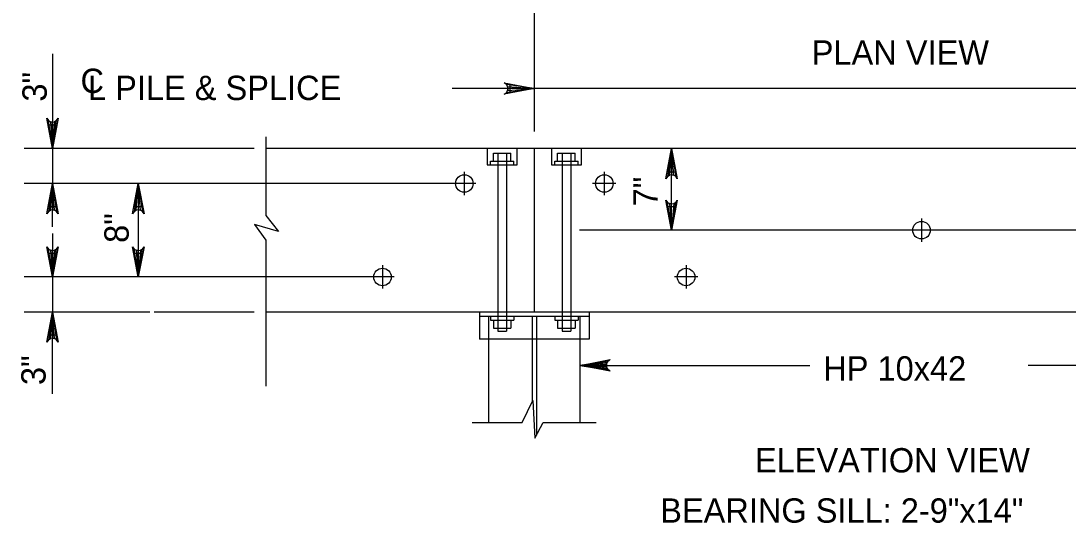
# Model space of a CAD drawing. Extents: x 638304 to 640306, y 296653 to 298435.
# Drawn here: x 639849.4 to 639978.5, y 298272.4 to 298334.2 of the extents above; entities that cross this region are included whole.
import ezdxf

# ---------------------------------------------------------------- set-up
doc = ezdxf.new("R2010")
doc.units = 0
for name, color, linetype in [('Level 3', 7, 'Continuous'), ('Level 4', 7, 'Continuous'), ('Level 5', 7, 'Continuous')]:
    doc.layers.add(name, color=color, linetype=linetype)

msp = doc.modelspace()

# ---------------------------------------------------------------- linework, layer by layer
at = {"layer": 'Level 3'}
for p, q in [((639879.57, 298319.97), (639879.57, 298310.27)), ((640041.22, 298318.53), (639879.57, 298318.53)), ((639907.63, 298316.95), (639907.63, 298317.94)), ((639907.63, 298317.94), (639909.79, 298317.94)), ((639908.17, 298317.94), (639908.17, 298296.02)), ((639909.25, 298317.94), (639909.25, 298296.02)), ((639909.79, 298316.95), (639909.79, 298317.94)), ((639912.67, 298318.53), (639912.67, 298298.38)), ((639915.55, 298316.95), (639915.55, 298317.94)), ((639915.55, 298317.94), (639917.71, 298317.94)), ((639916.09, 298317.94), (639916.09, 298296.02)), ((639917.17, 298317.94), (639917.17, 298296.02)), ((639917.71, 298316.95), (639917.71, 298317.94)), ((639907.27, 298316.5), (639907.27, 298316.95)), ((639907.27, 298316.95), (639910.15, 298316.95)), ((639910.15, 298316.5), (639910.15, 298316.95)), ((639915.19, 298316.5), (639915.19, 298316.95)), ((639915.19, 298316.95), (639918.07, 298316.95)), ((639918.07, 298316.5), (639918.07, 298316.95)), ((639904.03, 298315.65), (639904.03, 298312.78)), ((639921.3, 298315.65), (639921.3, 298312.78)), ((639922.74, 298314.22), (639919.86, 298314.22)), ((639879.57, 298310.27), (639881.15, 298308.32)), ((639878.18, 298309.16), (639879.57, 298307.25)), ((639881.15, 298308.32), (639878.18, 298309.16)), ((639960.4, 298309.9), (639960.4, 298307.02)), ((639879.57, 298307.25), (639879.57, 298289.23)), ((639893.96, 298304.14), (639893.96, 298301.26)), ((639931.38, 298304.14), (639931.38, 298301.26)), ((639932.81, 298302.7), (639929.94, 298302.7)), ((640041.22, 298298.38), (639879.57, 298298.38)), ((639905.91, 298298.38), (639905.91, 298295.02)), ((639919.43, 298297.82), (639905.91, 298297.82)), ((639907.03, 298297.82), (639907.03, 298295.02)), ((639907.27, 298297.82), (639907.27, 298297.37)), ((639907.27, 298297.37), (639910.15, 298297.37)), ((639907.63, 298297.37), (639907.63, 298296.38)), ((639909.79, 298297.37), (639909.79, 298296.38)), ((639910.15, 298297.82), (639910.15, 298297.37)), ((639912.39, 298297.82), (639912.39, 298287.3)), ((639912.95, 298297.82), (639912.95, 298283.2)), ((639915.19, 298297.82), (639915.19, 298297.37)), ((639915.19, 298297.37), (639918.07, 298297.37)), ((639915.55, 298297.37), (639915.55, 298296.38)), ((639917.71, 298297.37), (639917.71, 298296.38)), ((639918.07, 298297.82), (639918.07, 298297.37)), ((639918.3, 298297.82), (639918.3, 298295.02)), ((639919.43, 298298.38), (639919.43, 298295.02)), ((639907.63, 298296.38), (639909.79, 298296.38)), ((639908.17, 298296.02), (639909.25, 298296.02)), ((639915.55, 298296.38), (639917.71, 298296.38)), ((639916.09, 298296.02), (639917.17, 298296.02)), ((639919.43, 298295.02), (639905.91, 298295.02)), ((639907.03, 298295.02), (639907.03, 298284.75)), ((639918.3, 298295.02), (639918.3, 298284.75)), ((639911.18, 298284.75), (639912.47, 298287.48)), ((639912.47, 298287.48), (639912.75, 298282.83)), ((639905.03, 298284.75), (639911.18, 298284.75)), ((639912.75, 298282.83), (639913.77, 298284.75)), ((639913.77, 298284.75), (639920.29, 298284.75))]:
    msp.add_line(p, q, dxfattribs=at)
for points in [[(639906.87, 298316.5), (639910.55, 298316.5), (639910.55, 298318.53), (639906.87, 298318.53)], [(639914.78, 298316.5), (639918.47, 298316.5), (639918.47, 298318.53), (639914.78, 298318.53)]]:
    msp.add_lwpolyline(points, close=True, dxfattribs=at)
for centre in [(639904.04, 298314.22), (639921.3, 298314.22), (639960.4, 298308.46), (639893.96, 298302.7), (639931.38, 298302.7)]:
    msp.add_circle(centre, 1.08, dxfattribs=at)
at = {"layer": 'Level 4'}
for p, q in [((639912.67, 298356.96), (639912.67, 298320.62)), ((639853.29, 298330.18), (639853.29, 298318.53)), ((640008.13, 298325.91), (639902.54, 298325.91)), ((639878.13, 298318.53), (639849.78, 298318.53)), ((639853.29, 298318.53), (639853.29, 298314.22)), ((639929.6, 298308.46), (639929.6, 298318.53)), ((639905.47, 298314.22), (639849.78, 298314.22)), ((639853.29, 298308.86), (639853.29, 298314.22)), ((639863.86, 298314.22), (639863.86, 298302.7)), ((639853.29, 298308.04), (639853.29, 298302.7)), ((639993.91, 298308.46), (639918.23, 298308.46)), ((639895.4, 298302.7), (639849.78, 298302.7)), ((639853.29, 298302.7), (639853.29, 298298.38)), ((639865.29, 298298.38), (639849.78, 298298.38)), ((639853.29, 298288.31), (639853.29, 298298.38)), ((639878.13, 298298.38), (639865.8, 298298.38))]:
    msp.add_line(p, q, dxfattribs=at)
for points in [[(639912.67, 298325.91), (639908.95, 298325.21), (639909.23, 298325.41), (639909.38, 298325.66), (639909.43, 298325.91), (639909.38, 298326.16), (639909.23, 298326.41), (639908.95, 298326.61), (639912.67, 298325.91), (639909.23, 298326.41), (639909.38, 298326.16), (639912.67, 298325.91), (639909.43, 298325.91), (639909.38, 298325.66), (639912.67, 298325.91), (639909.23, 298325.41)], [(639853.29, 298318.53), (639852.59, 298322.25), (639852.79, 298321.97), (639853.04, 298321.82), (639853.29, 298321.78), (639853.54, 298321.82), (639853.79, 298321.97), (639853.99, 298322.25), (639853.29, 298318.53), (639853.79, 298321.97), (639853.54, 298321.82), (639853.29, 298318.53), (639853.29, 298321.78), (639853.04, 298321.82), (639853.29, 298318.53), (639852.79, 298321.97)], [(639929.6, 298318.53), (639930.3, 298314.81), (639930.1, 298315.1), (639929.85, 298315.24), (639929.6, 298315.29), (639929.35, 298315.24), (639929.1, 298315.1), (639928.9, 298314.81), (639929.6, 298318.53), (639929.1, 298315.1), (639929.35, 298315.24), (639929.6, 298318.53), (639929.6, 298315.29), (639929.85, 298315.24), (639929.6, 298318.53), (639930.1, 298315.1)], [(639853.29, 298314.22), (639853.99, 298310.49), (639853.79, 298310.78), (639853.54, 298310.93), (639853.29, 298310.97), (639853.04, 298310.93), (639852.79, 298310.78), (639852.59, 298310.49), (639853.29, 298314.22), (639852.79, 298310.78), (639853.04, 298310.93), (639853.29, 298314.22), (639853.29, 298310.97), (639853.54, 298310.93), (639853.29, 298314.22), (639853.79, 298310.78)], [(639863.86, 298314.22), (639864.56, 298310.49), (639864.36, 298310.78), (639864.11, 298310.93), (639863.86, 298310.97), (639863.61, 298310.93), (639863.36, 298310.78), (639863.16, 298310.49), (639863.86, 298314.22), (639863.36, 298310.78), (639863.61, 298310.93), (639863.86, 298314.22), (639863.86, 298310.97), (639864.11, 298310.93), (639863.86, 298314.22), (639864.36, 298310.78)], [(639929.6, 298308.46), (639928.9, 298312.18), (639929.1, 298311.89), (639929.35, 298311.74), (639929.6, 298311.7), (639929.85, 298311.74), (639930.1, 298311.89), (639930.3, 298312.18), (639929.6, 298308.46), (639930.1, 298311.89), (639929.85, 298311.74), (639929.6, 298308.46), (639929.6, 298311.7), (639929.35, 298311.74), (639929.6, 298308.46), (639929.1, 298311.89)], [(639853.29, 298302.7), (639852.59, 298306.42), (639852.79, 298306.14), (639853.04, 298305.99), (639853.29, 298305.95), (639853.54, 298305.99), (639853.79, 298306.14), (639853.99, 298306.42), (639853.29, 298302.7), (639853.79, 298306.14), (639853.54, 298305.99), (639853.29, 298302.7), (639853.29, 298305.95), (639853.04, 298305.99), (639853.29, 298302.7), (639852.79, 298306.14)], [(639863.86, 298302.7), (639863.16, 298306.42), (639863.36, 298306.14), (639863.61, 298305.99), (639863.86, 298305.95), (639864.11, 298305.99), (639864.36, 298306.14), (639864.56, 298306.42), (639863.86, 298302.7), (639864.36, 298306.14), (639864.11, 298305.99), (639863.86, 298302.7), (639863.86, 298305.95), (639863.61, 298305.99), (639863.86, 298302.7), (639863.36, 298306.14)], [(639853.29, 298298.38), (639853.99, 298294.66), (639853.79, 298294.95), (639853.54, 298295.1), (639853.29, 298295.14), (639853.04, 298295.1), (639852.79, 298294.95), (639852.59, 298294.66), (639853.29, 298298.38), (639852.79, 298294.95), (639853.04, 298295.1), (639853.29, 298298.38), (639853.29, 298295.14), (639853.54, 298295.1), (639853.29, 298298.38), (639853.79, 298294.95)], [(639918.31, 298291.81), (639922.03, 298292.51), (639921.88, 298292.41), (639921.74, 298292.31), (639921.67, 298292.19), (639921.59, 298292.06), (639921.57, 298291.94), (639921.55, 298291.81), (639921.57, 298291.69), (639921.59, 298291.56), (639921.67, 298291.44), (639921.74, 298291.31), (639921.88, 298291.21), (639922.03, 298291.11), (639918.31, 298291.81), (639921.88, 298291.21), (639921.74, 298291.31), (639918.31, 298291.81), (639921.67, 298291.44), (639921.59, 298291.56), (639918.31, 298291.81), (639921.57, 298291.69), (639921.55, 298291.81), (639918.31, 298291.81), (639921.57, 298291.94), (639921.59, 298292.06), (639918.31, 298291.81), (639921.67, 298292.19), (639921.74, 298292.31), (639918.31, 298291.81), (639921.88, 298292.41)], [(639918.31, 298291.81), (639946.62, 298291.81)], [(640002.49, 298291.81), (639973.55, 298291.81)]]:
    msp.add_lwpolyline(points, dxfattribs=at)
for points in [[(639909.67, 298326.39), (639909.67, 298325.43), (639912.55, 298325.91)], [(639853.77, 298321.41), (639852.81, 298321.41), (639853.29, 298318.53)], [(639929.12, 298315.65), (639930.08, 298315.65), (639929.6, 298318.53)], [(639853.77, 298311.34), (639852.81, 298311.34), (639853.29, 298314.22)], [(639864.34, 298311.34), (639863.38, 298311.34), (639863.86, 298314.22)], [(639930.08, 298311.34), (639929.12, 298311.34), (639929.6, 298308.46)], [(639853.77, 298305.58), (639852.81, 298305.58), (639853.29, 298302.7)], [(639864.34, 298305.58), (639863.38, 298305.58), (639863.86, 298302.7)], [(639853.77, 298295.51), (639852.81, 298295.51), (639853.29, 298298.38)]]:
    msp.add_lwpolyline(points, close=True, dxfattribs=at)

# ---------------------------------------------------------------- texts
for s, height, p in [('PLAN VIEW', 3, (639946.87, 298328.86)), ('C', 3, (639856.73, 298325.37)), ('L PILE & SPLICE', 3.0001, (639857.66, 298324.5)), ('HP 10x42', 3, (639948.29, 298289.93)), ('ELEVATION VIEW', 3.0001, (639939.87, 298278.61))]:
    msp.add_text(s, height=height, dxfattribs=at).set_placement(p)
at = {"layer": 'Level 5'}
for s, p in [('3"', (639852.57, 298324.31)), ('7"', (639927.89, 298311.4)), ('8"', (639862.67, 298306.9)), ('3"', (639852.43, 298289.38))]:
    msp.add_text(s, height=3, rotation=90, dxfattribs=at).set_placement(p)
msp.add_text('BEARING SILL: 2-9"x14"', height=3.0001, dxfattribs=at).set_placement((639928.19, 298272.42))

doc.saveas('drawing.dxf')
